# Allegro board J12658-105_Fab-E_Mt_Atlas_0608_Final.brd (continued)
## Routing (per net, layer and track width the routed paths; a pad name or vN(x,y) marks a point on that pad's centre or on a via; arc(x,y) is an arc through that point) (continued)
MUX_CTRL_3: length 30.1
  TOP w0.127: v1(28.19,27.3) 28.06,27.44 U28.1
  L3_SIG w0.127: SW4.3 16.64,14.22 16.64,16.13 17.16,16.65 17.89,16.65 17.91,16.64 18.35,16.64 18.81,17.09 18.81,19.42 v1(18.54,19.69) ; v1(28.19,27.3) 28.19,26.78 27.62,26.2 27.62,21.39 27.37,21.14 v1(26.49,21.14)
  L4_SIG w0.127: v1(26.49,21.14) 25.04,19.69 23.93,19.69 23.91,19.67 23.59,19.67 23.57,19.69 v1(18.54,19.69)
  BOTTOM w0.127: R246.2 20.32,12.19 20,11.87 18.99,11.87 SW4.3
MUX_CTRL_4: length 45.9
  TOP w0.127: U19.1 v1(15.62,41.77)
  L3_SIG w0.127: v1(11.18,42.13) 11.44,41.87 11.44,38.74 11.13,38.43 11.13,38.23 11.1,38.2 11.1,37.87 11.13,37.85 11.13,36.81 11.46,36.48 11.46,36.44 11.62,36.28 11.62,14.94 13.85,12.71 13.85,11.61 14.15,11.32 14.78,11.32 15.18,10.92 17.4,10.92 SW4.4
  L4_SIG w0.127: v1(11.18,42.13) 11.54,41.77 v1(15.62,41.77)
  BOTTOM w0.127: SW4.4 18.67,11.18 R249.2
PB0_BTN: length 2.9
  TOP w0.127: SW1.2 38.99,67.46 v1(40.17,67.46)
  BOTTOM w0.127: v1(40.17,67.46) 40.17,68.09 R136.1 R137.2
PB1_BTN: length 2.8
  TOP w0.127: v1(42.35,67.44) 42.38,67.46 43.43,67.46 SW2.2
  BOTTOM w0.127: R135.1 R134.2 42.48,67.56 v1(42.35,67.44)
PLT_REG_EN: length 2.9
  TOP w0.127: U22.K3 v1(36.58,37.17)
  BOTTOM w0.127: v1(36.58,37.17) 36.99,37.57 37.57,37.57 38.16,38.16 R262.2
RESET_BTN: length 4.2
  TOP w0.127: S1.2 65.75,74.1 v1(64.85,74.1)
  BOTTOM w0.127: U31.2 64.92,72.27 64.77,72.42 64.77,72.96 64.29,73.44 Q1.3 64.29,73.76 64.64,74.1 v1(64.85,74.1)
RF_1: length 1.9
  TOP w0.229: U29.17 43.82,14.55 43.42,14.15 43.42,13.67 RF1.4
RF_2: length 1.9
  TOP w0.229: RF1.3 45.22,13.67 45.22,14.15 44.82,14.55 U29.19
RF_3: length 1.5
  TOP w0.229: L7.1 46.51,12.37 RF1.1
RF_4: length 2.3
  TOP w0.229: L8.1 L7.2
RF_5: length 1.6
  TOP w0.254: FL1.1 44.7,9.2 44.72,9.22 L8.2
RF_6: length 1.3
  TOP w0.254: L9.1 45.85,8.2 FL1.4
RF_ANT: length 4.9
  TOP w0.229: L10.2 C43.1 44.89,3.15 RF2.3 RF2.1
RF_ANT_R: length 2.8
  TOP w0.229: R118.2 R120.1 C42.1 L10.1
RF_EXT_ANT: length 4
  TOP w0.229: J13.1 44.2,6.86 44.58,7.24 R120.2
RSTOUT_N: length 8.1
  TOP w0.127: v1(44.39,59.75) 44.08,59.75 43.61,59.29 U11.5 ; R8.2 v1(45.97,64.52)
  L3_SIG w0.127: v1(45.97,64.52) 45.97,63.5 44.39,61.91 v1(44.39,59.75)
TMP_I2C_ADDRESS: length 3.9
  TOP w0.127: v1(42.55,29.85) 42.55,30.35 42.81,30.62 U21.4
  BOTTOM w0.127: R204.1 43.37,29.02 v1(42.55,29.85) 42.48,29.91 R203.2
UART1_CTS_FTD: length 52.5
  TOP w0.127: U20.10 22.12,43.97 21.59,43.43 21.34,43.43 20.95,43.81 20.95,44.45 v1(21.46,44.96) ; v1(54.67,54.42) 55.56,54.42 56.19,55.05 U9.14
  L3_SIG w0.127: v1(21.59,53.9) 21.13,53.44 21.13,48.57 21.94,47.77 21.94,45.43 v1(21.46,44.96)
  L4_SIG w0.127: v1(54.67,54.42) 54.67,53.09 54.37,52.78 53.78,52.78 52.84,51.84 50.91,51.84 50.31,51.23 48.21,51.23 48.08,51.36 46.45,51.36 46.33,51.23 43.21,51.23 42.98,51.46 42.98,51.52 40.65,53.84 38.99,53.84 38.66,53.52 35.3,53.52 34.68,54.14 21.83,54.14 v1(21.59,53.9)
UART1_CTS_HDR_HDR: length 5.9
  TOP w0.203: R21.1 64.77,54.61 66.04,55.88
UART1_RTS_FTD: length 52.2
  TOP w0.127: U20.13 24.13,45.92 24.51,46.3 v1(24.51,47.88) ; v1(58.04,51.12) 58.04,51.82 56.58,53.28 55.18,53.28 54.1,54.36 54.1,55.75 54.39,56.04 U9.12
  L4_SIG w0.127: v1(58.04,51.12) 58.46,51.12 59.31,50.27 59.31,49.42 56.5,46.61 54.29,46.61 54.03,46.34 50.04,46.34 49.25,47.13 48.92,47.13 48.64,46.85 43.63,46.85 42.62,47.87 36.72,47.87 35.93,48.65 31.64,48.65 30.75,47.77 26.55,47.77 26.42,47.64 25.9,47.64 25.66,47.88 v1(24.51,47.88)
UART1_RTS_HDR_HDR: length 5.9
  TOP w0.203: 66.04,53.34 64.77,52.07 R26.1
UART1_RXD_FTD: length 65.8
  TOP w0.127: v1(18.67,44.96) 18.33,44.62 U20.6 ; v1(56.52,54.74) 56.59,54.81 U9.15
  L3_SIG w0.127: v1(55.56,60.39) 55.56,55.69 v1(56.52,54.74) ; v1(20.19,58.04) 19.94,57.78 17.21,57.78 16.84,57.42 16.84,57.02 17.14,56.72 18.59,56.72 20.27,55.04 20.27,53.54 18.62,51.89 18.62,49.27 19.15,48.73 19.15,45.44 v1(18.67,44.96)
  L4_SIG w0.127: v1(55.56,60.39) 55.56,60.5 53.95,62.12 46.62,62.12 45.72,61.21 39.88,61.21 38.61,59.94 29.46,59.94 28.99,59.47 21.63,59.47 v1(20.19,58.04)
UART1_RXD_HDR_HDR: length 5.9
  TOP w0.203: 66.04,58.42 64.77,57.15 R18.1
UART1_TXD_FTD: length 65.9
  TOP w0.127: U9.13 54.95,55.47 v1(54.86,55.56) ; v1(18.67,46.99) 18.25,46.57 U20.3
  L3_SIG w0.127: v1(18.67,46.99) 18.05,47.61 18.05,51.46 18.05,51.64 18.75,52.35 18.75,53.44 18.35,53.85 17.84,53.85 17.69,53.69 17.12,53.69 16.92,53.89 16.92,54.57 16.51,54.98 16.51,57.98 17.21,58.67 19.56,58.67 v1(19.88,58.99) ; v1(54.86,55.56) 54.36,56.07 54.36,59.82 55.44,60.9 v1(56.13,60.9)
  L4_SIG w0.127: v1(19.88,58.99) 20.59,59.7 24.74,59.7 25.36,60.32 38.16,60.32 39.37,61.53 45.71,61.53 47.82,63.64 53.39,63.64 v1(56.13,60.9)
UART1_TXD_HDR_HDR: length 5.9
  TOP w0.203: 66.04,60.96 64.77,59.69 R14.1
UART_MUX_SEL: length 4.6
  TOP w0.127: v1(18.67,48.01) 18.53,47.87 U20.1
  BOTTOM w0.127: 17.65,45.97 R188.1 v1(18.67,48.01)
UART_RX_DIR: length 2.9
  TOP w0.203: U9.5 56.99,58 57.66,58.67 v1(57.91,58.67)
  BOTTOM w0.127: R146.1 57.66,58.67 v1(57.91,58.67)
UART_TX_DIR: length 3.1
  TOP w0.127: v1(57.91,57.78) 57.37,57.24 U9.4
  BOTTOM w0.127: v1(57.91,57.78) 58.44,58.32 58.44,58.9 R145.2
UNNAMED_6_HDR2X22_I187_37: length 13
  BOTTOM w0.203: R241.2 12.17,14.48 11.41,13.72 11.41,12.64 10.52,11.75 7.49,11.75 7.24,11.49 3.87,11.49 J15.37
UNNAMED_11_RES_I77_B: length 2.4
  TOP w0.127: U21.3 43.77,32.62 43.43,32.96 v1(43.43,33.59)
  BOTTOM w0.127: R197.2 v1(43.43,33.59)
UNNAMED_12_CAP_I18_A: length 3.9
  TOP w0.127: C32.1 48.13,21.34 48.01,21.21 48.01,19.37 47.42,18.78 U29.27
UNNAMED_12_CC2520RHDT_I96_RBIAS: length 1.9
  TOP w0.127: U29.23 47.74,16.78 48.01,16.51 R110.1
UNNAMED_13_CAP_I46_A: length 4
  TOP w0.127: U30.41 v1(19.69,5.72)
  BOTTOM w0.127: v1(19.69,5.72) 19.69,6.73 20.19,7.24 C95.1
UNNAMED_14_LED_I15_C: length 1
  TOP w0.127: D2.2 R1.1
UNNAMED_15_RES_I26_B: length 1.9
  TOP w0.127: U15.7 18.92,50.48 v1(19.18,50.74)
  BOTTOM w0.127: R163.2 18.35,50.74 v1(19.18,50.74)
UNNAMED_15_RES_I27_B: length 2.8
  TOP w0.127: U15.3 14.86,49.98 v1(14.61,49.72)
  BOTTOM w0.127: R165.2 15.56,50.16 15.11,49.72 v1(14.61,49.72)
UNNAMED_17_FERRITE_I54_A: length 8
  TOP w0.508: FB3.1 14.22,68.2 12.26,70.17 12.26,72.96 J3.3
UNNAMED_18_DMN1150UFB7B_I109_3: length 0.9
  TOP w0.127: R133.2 55.82,69.02 Q2.3
UNNAMED_18_RES_I145_B: length 3.1
  TOP w0.508: R7.2 J6.1
UNNAMED_19_CAP_I58_A: length 3
  TOP w0.127: U11.6 43.11,57.15 v1(42.35,56.39)
  BOTTOM w0.127: C62.1 v1(42.35,56.39)
UNNAMED_19_CAP_I85_A: length 3
  TOP w0.508: U5.5 31.75,64.65 v1(31.81,64.58) FB5.2
  BOTTOM w0.381: v1(31.81,64.58) 31.88,64.64 C51.1
UNNAMED_19_LED_I28_C: length 1.2
  TOP w0.127: D1.2 R4.1
UNNAMED_19_RES_I88_B: length 3
  TOP w0.127: v1(29.85,67.07) 29.85,67.07 U5.3
  BOTTOM w0.127: R138.2 30.1,67.88 29.85,67.64 v1(29.85,67.07)
USB_FTD_DM: length 11.9
  TOP w0.21: v1(48.32,60.83) 48.09,61.07 48.09,61.24 48.2,61.35 L2.2 ; U11.8 42.11,59.61 v1(41.97,59.75)
  L3_SIG w0.152: v1(41.97,59.75) 41.97,58.98 42.91,58.05 44.86,58.05 45.6,58.79 47.5,58.79 48.12,59.42 48.12,60.63 v1(48.32,60.83)
USB_FTD_DP: length 11.8
  TOP w0.21: v1(42.86,59.75) 42.85,59.75 42.61,59.51 U11.7 ; L2.3 47.65,61.39 47.73,61.3 47.73,60.94 v1(47.62,60.83)
  L3_SIG w0.152: v1(42.86,59.75) 42.86,60.01 42.74,60.12 42.59,60.12 42.42,59.96 42.42,58.96 43.03,58.35 44.73,58.35 45.47,59.09 47.37,59.09 47.82,59.54 47.82,60.64 v1(47.62,60.83)
V_BATT: length 12.2
  TOP w0.508: v1(21.97,64.26) 21.21,63.5 F1.2
  BOTTOM w0.508: v1(21.97,64.26) 22.48,64.77 22.48,69.08 J4.2
V_BATT_FUSE: length 3.1
  TOP w0.254: 19.05,60.64 D8.2
  TOP w0.508: F1.1 19.56,59.69 19.05,60.2 19.05,60.64
V_BATT_FUSE_D: length 15.2
  TOP w0.254: 19.05,61.72 D8.1
  TOP w0.508: 19.05,61.72 19.05,62.74 v1(18.67,63.12) ; 16.37,67.5 15.8,66.93 FB3.2 ; 16.37,67.5 v1(17.46,67.5) ; 16.37,67.5 16.35,67.51 16.35,69.88 14.99,71.25 J5.3
  BOTTOM w0.508: v1(18.67,63.12) 18.67,64.9 18.73,64.96 18.73,66.23 v1(17.46,67.5)
V_BB_3P8: length 65.6
  TOP w0.381: R3.1 R2.1 39.5,71.5 v1(39.24,71.75) ; v1(7.76,61.77) R13.1
  L4_SIG w0.635: J3.1 6.41,74.17 5.4,73.15 5.4,59.37 v1(7.51,57.26) v1(8.33,57.26)
  BOTTOM w0.305: J3.1 9.82,72.73 16.34,72.73 18.16,74.55 26.92,74.55 28.89,72.58 28.89,70.8 29.46,70.23 36.39,70.23 36.83,69.79 38.73,69.79 39.24,70.29 v1(39.24,71.75)
  BOTTOM w0.381: v1(7.76,61.77) 7.51,61.51 v1(7.51,57.26)
V_BB_EN: length 4
  TOP w0.127: v1(13.29,61.38) 13.29,60.88 13.07,60.66 U40.6
  BOTTOM w0.254: R15.2 14.05,60.62 v1(13.29,61.38)
V_BB_FB: length 2.1
  TOP w0.305: U40.10 9.71,60.66 R144.1
  TOP w0.381: R13.2 R144.1
V_BB_L1: length 0.7
  TOP w0.254: 12.21,57.7 12.12,57.79 U40.4
V_BB_L2: length 0.7
  TOP w0.254: 11.13,57.64 11.13,58.33 U40.2
V_BB_PS: length 3.8
  TOP w0.127: v1(12.5,61.39) 12.53,61.39 12.53,61.38 12.27,61.38 12.12,61.23 U40.7
  BOTTOM w0.254: R142.1 12.14,61.03 v1(12.5,61.39) 13.1,60.79 R143.2
V_BB_VINA: length 1.2
  TOP w0.254: U40.8 11.62,61.62 C55.1
VOLT_SEL: length 84.7
  TOP w0.127: v1(52.45,69.91) 53.11,69.25 Q2.1 ; v1(47.75,30.99) 47.77,31.01 U18.2
  TOP w0.203: U24.1 43.69,29.59 v1(43.43,29.85)
  L3_SIG w0.127: v1(52.45,69.91) 52.45,69.42 51.56,68.53 51.53,68.53 50.24,67.24 50.24,63.96 50.04,63.75 49.47,63.75 49.07,63.36 49.07,58.56 47.17,56.65 47.17,43.83 48.36,42.63 48.36,31.6 v1(47.75,30.99) 47.39,30.99 46.49,31.89 45.43,31.89 43.43,29.89 v1(43.43,29.85)
  L4_SIG w0.127: v1(52.45,69.91) 52.44,69.9 51.63,69.9 50.05,68.32 26.92,68.32 v1(25.78,67.18)
  BOTTOM w0.127: J6.2 25.27,63.25 25.78,63.75 v1(25.78,67.18)
VOLT_SEL_N: length 4.5
  TOP w0.127: U24.4 44.79,28 46,28 46.52,27.48 47.28,27.48 47.77,27.97 U8.2
VSYS: length 196.6
  TOP w0.203: U8.1 47.37,28.17 47.14,27.94 v1(46.74,27.94) ; U24.5 44.54,29.49 44.64,29.59 v1(45.09,29.59) ; v1(46.74,30.99) 47.37,31.62 U18.1
  TOP w0.254: U27.1 v1(51.44,30.99)
  TOP w0.381: U1.6 60.98,74.08 v1(60.99,74.07) ; U36.5 62.73,73.97 v1(62.74,73.98) ; 60.96,71.12 60.64,70.8 U2.6 ; 60.96,71.12 61.19,70.89 U36.1 ; 60.96,71.12 v1(60.96,71.25)
  TOP w0.508: R7.1 27.24,67.63 25.56,69.31 v1(24.19,69.31) ; SW3.2 6.54,66.61 FB1.1 7.41,67.62 7.88,68.09 v1(7.88,69.59)
  L3_SIG w0.381: v1(51.44,30.99) 49.22,28.77 47.57,28.77 ; 47.57,28.77 v1(46.74,27.94) v1(45.09,29.59) ; 47.57,28.77 47.57,30.28 46.86,30.99 v1(46.74,30.99)
  L3_SIG w0.635: v1(54.23,67.31) 54.23,66.61 v1(53.98,66.36) 53.98,64.1 56.35,61.72 59.27,61.72 62.15,58.84 62.15,33.34 v1(61.4,32.59) v1(61.4,31.56)
  L4_SIG w0.508: v1(60.96,71.25) 60.01,72.2 60.01,74.07 ; 60.01,74.07 v1(60.99,74.07) 61.07,73.99 61.2,73.99 61.21,73.98 v1(62.74,73.98) 63.18,73.98 64.01,74.8 v1(64.77,74.8) ; 60.01,74.07 58.62,74.07 57.66,75.03 56.62,75.03 55.5,73.91 v1(53.21,73.91) ; v1(51.44,30.99) 50.8,31.62 50.8,32.05 50.22,32.64 46.29,32.64 46.16,32.51 v1(42.55,32.51) v1(41.72,32.51)
  L4_SIG w0.635: 53.21,73.41 52.2,73.41 51.94,73.15 28.07,73.15 24.22,69.31 v1(24.19,69.31) 18.32,69.31 14.92,72.71 7.81,72.71 6.98,71.88 6.98,70.48 v1(7.88,69.59) ; 53.21,73.41 v1(53.21,72.83) ; 53.21,73.41 v1(53.21,73.91) ; v1(61.4,32.59) v1(61.4,31.56) 60.83,31.56 59.05,33.34 57.75,33.34 55.4,30.99 v1(51.44,30.99)
  BOTTOM w0.254: R279.1 9.14,56.07 8.95,56.26 6.86,56.26 6.1,57.02 6.1,60.83 SW3.2
  BOTTOM w0.381: C103.1 v1(62.74,73.98) ; C72.1 v1(46.74,27.94) ; v1(64.77,74.8) 65.15,74.8 65.53,74.42 R125.1 ; C90.1 51.37,30.92 v1(51.44,30.99) ; R131.1 60.39,71.25 v1(60.96,71.25) 61.72,71.25 C48.1 ; C99.1 v1(46.74,30.99) ; C91.1 v1(41.72,32.51) v1(42.55,32.51) ; C100.1 44.64,29.15 v1(45.09,29.59) ; R124.1 60.49,74.07 v1(60.99,74.07) 61.43,74.07 C45.1
  BOTTOM w0.635: v1(53.21,73.91) v1(53.21,72.83) 53.21,68.33 v1(54.23,67.31) 54.04,67.12 54.04,66.42 v1(53.98,66.36)
VSYS_ADC_SENSE: length 3.2
  BOTTOM w0.127: R280.1 C97.1 R127.2 R279.2
VSYS_DISCH: length 3.3
  TOP w0.508: SW3.3 6.01,61 R17.1
VSYS_SENSE: length 13.7
  TOP w0.508: SW3.1 3.43,67.7 4.62,68.89 6.54,68.89 FB1.2 6.54,72.07 7.16,72.7 9.45,72.7 J3.2
XVREF: length 59.9
  TOP w0.127: R42.2 v1(54.61,44.2)
  L3_SIG w0.127: v1(54.86,49.15) 54.34,48.63 54.34,47.23 54.24,47.13 54.24,44.56 v1(54.61,44.2) 55.09,44.2 55.8,43.49 55.8,11.35 54.99,10.54 v1(53.91,10.54)
  L4_SIG w0.127: v1(54.86,49.15) 54.17,49.15 53.94,48.92 53.14,48.92 52.92,48.71 47.82,48.71 47.11,47.99 44.14,47.99 43.31,48.82 40.06,48.82 v1(39.5,48.26)
  BOTTOM w0.127: R252.2 v1(53.91,10.54) ; R169.1 v1(39.5,48.26)
XVREF_HDR: length 11.8
  BOTTOM w0.203: R252.1 56.52,10.54 57.9,9.16 60.87,9.16 61.21,8.83 64.83,8.83 J14.46

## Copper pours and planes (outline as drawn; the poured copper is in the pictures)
AVDD_B_RADIO on TOP: 40.39,14.48 40.39,13.91 40.89,13.91 40.89,14.41 41.4,14.41 41.4,13.91 41.91,13.91 41.91,14.41 42.23,14.41 42.23,16.38 41.47,16.38 41.47,15.56
GND on TOP (solid shape): 10.22,60.12 11.02,60.12 11.02,60.13 11.22,60.13 11.22,60.12 13.03,60.12 13.03,60.13 14.48,60.13 14.61,60.01 14.61,59.18 13.84,59.18 13.84,59.1 13.35,59.1 13.16,58.91 10.62,58.91 10.49,59.04 8.66,59.04 8.66,60.06 8.74,60.13 10.22,60.13
GND on BOTTOM (solid shape): 12.59,59.67 12.59,59.31 12.46,59.18 8.38,59.18 8.38,59.94 12.32,59.94
GND on TOP: 48.13,4.55 48.13,8.64 47.88,8.89 47.88,11.94 47.5,12.32 44.32,12.32 44.32,11.68 44.07,11.68 44.07,9.78 43.05,9.78 42.67,9.4 42.67,8.89 39.05,8.89 39.05,4.55
GND on TOP: 68.01,1.21 67.44,0.64 53.34,0.64 53.34,4.55 15.24,4.55 15.24,0.64 1.08,0.64 0.57,1.14 0.57,74.99 1.21,75.63 67.37,75.63 68.01,74.99 ; 25 cut-outs
GND on BOTTOM: 68.01,1.21 67.44,0.64 53.34,0.64 53.34,4.7 15.24,4.7 15.24,0.64 1.08,0.64 0.57,1.14 0.57,74.99 1.21,75.63 67.37,75.63 68.01,74.99 ; 17 cut-outs
GND on LAYER2_GND: 1.03,0.64 0.64,1.03 0.64,75.17 1.03,75.56 67.55,75.56 67.94,75.17 67.94,1.03 67.55,0.64 53.34,0.64 53.34,4.64 24.51,4.64 24.51,0.64
VBAT_SOC on TOP: 39.37,33.4 39.05,33.72 38.35,33.72 38.21,33.57 38.21,31.54 37.98,31.3 37.97,30.1 38.42,29.65 39.12,29.65 39.37,29.91
VBAT_SOC on L3_SIG: 36.45,36.96 38.3,36.96 39.27,35.99 39.27,31.46 38.86,31.05 37.78,31.05 37.3,31.54 37.3,33.81 36.2,34.91 36.2,36.7
VCC_AON_1P8 on LAYER5_PWR: 36.76,30.35 35.56,31.55 35.56,33.45 33.59,35.42 33.59,39.43 36.07,39.43 36.07,37.6 36.65,37.02 37.35,37.02 39.88,34.49 39.88,31.68 38.56,30.35
VCC_HOST_1P8 on TOP: 41.97,40.83 41.53,41.27 41.53,42.65 45.11,42.65 45.34,42.42 45.34,41.08 45.09,40.83
VCC_HOST_1P8 on LAYER5_PWR: 36.32,39.31 36.32,39.69 33.59,39.69 33.59,41.85 40.12,41.85 41.84,43.56 45.41,43.56 45.59,43.38 45.59,40.51 42.56,40.51 41.73,39.69 38.05,39.69 37.67,39.31
VCC_IO on LAYER5_PWR: 6.73,0.64 6.73,64.46 10.85,68.58 35.99,68.58 37.77,70.36 52.63,70.36 53.77,71.5 56.64,71.5 57.59,72.45 58.48,72.45 58.61,72.33 58.61,71.64 61.72,68.53 61.72,65.15 41.86,65.15 36.27,59.56 30.68,59.56 29.84,58.73 29.84,56.45 30.92,55.37 31.69,55.37 32.32,56.01 32.83,56.01 33.4,55.44 33.4,54.48 35.18,52.7 38.05,52.7 41.86,48.89 47.05,48.89 47.75,48.2 47.75,46.8 48.58,45.97 55.56,45.97 57.4,47.82 57.4,56.01 61.72,56.01 61.72,0.64 53.34,0.64 53.34,4.7 15.24,4.7 15.24,0.64 ; 2 cut-outs
VCC_IO_AON on BOTTOM: 35.12,41.78 35.12,43.81 34.73,44.2 33.78,44.2 33.46,43.88 33.46,41.59 32.43,40.56 32.43,40.04 32.26,39.87 32.26,39.5 32.32,39.43 32.77,39.43 32.78,39.45 33.36,39.45 33.78,39.88 33.78,40.45
VCC_PLT_1P8 on TOP: 44.7,34.73 41.85,34.73 41.47,35.12 41.47,36.77 41.78,37.08 43.56,37.08 43.75,36.89 43.75,36.32 43.94,36.13 44.64,36.13 44.83,35.94 44.83,34.86
VCC_PLT_1P8 on LAYER5_PWR: 40.06,34.67 37.45,37.27 36.76,37.27 36.32,37.71 36.32,38.29 38.24,38.29 38.62,37.91 39.32,37.91 40.02,37.21 45.59,37.21 45.59,34.67
VCC_PLT_3P3 on TOP: 41.85,37.66 43.94,37.66 43.94,39.56 44.01,39.62 44.01,40.32 43.81,40.51 42.04,40.51 41.47,39.94 41.47,38.04
VCC_PLT_3P3 on LAYER5_PWR: 40.12,37.46 39.42,38.16 38.72,38.16 38.34,38.54 36.32,38.54 36.32,39.05 37.77,39.05 38.15,39.43 41.84,39.43 42.66,40.26 45.59,40.26 45.59,37.46
VCC_RADIO on LAYER5_PWR: 36.45,11.3 36.45,26.29 51.75,26.29 51.75,11.42 51.64,11.3
VDD_HDR on L3_SIG: 59.18,68.83 10.67,68.83 6.48,64.64 6.48,0.64 1.08,0.64 0.63,1.08 0.63,75.12 1.08,75.56 67.44,75.56 68.07,74.93 68.07,1.21 67.5,0.64 61.98,0.64 61.98,66.04
VDD_HDR on LAYER5_PWR: 1.03,0.64 0.26,1.41 0.26,74.79 1.15,75.69 67.43,75.69 68.32,74.79 68.32,1.41 67.55,0.64 61.98,0.64 61.98,68.63 58.86,71.75 58.86,72.46 58.61,72.71 57.47,72.71 56.52,71.75 53.67,71.75 52.53,70.61 37.67,70.61 35.89,68.83 10.74,68.83 6.48,64.57 6.48,0.64
(no net) on TOP: 13.16,58.91 13.35,59.1 14.61,59.1 14.61,60.01 14.48,60.13 8.74,60.13 8.66,60.06 8.66,59.04 10.49,59.04 10.62,58.91
(no net) on TOP: 12.02,58.59 12.02,57 12.34,56.69 12.34,54.08 13.16,54.08 13.16,57 12.27,57.89 12.27,58.59
(no net) on TOP: 10.75,58.53 7.11,58.53 7.11,57.21 7.32,57 9.67,57 10.75,58.08
(no net) on TOP: 11.26,58.59 11,58.59 11,57.83 10.18,57 10.18,54.08 10.94,54.08 10.94,56.75 11.26,57.07
(no net) on TOP: 12.46,58.65 14.54,58.65 14.54,57.78 12.83,57.78 12.79,57.75 12.46,58.08
(no net) on BOTTOM: 12.32,59.94 8.38,59.94 8.38,59.18 12.46,59.18 12.59,59.31 12.59,59.67
(no net) on BOTTOM: 8.38,58.55 8.25,58.42 8.25,58.04 7.75,57.53 7.38,57.53 7.26,57.4 7.26,57.19 7.43,57.02 9.4,57.02 10.29,57.91 10.29,58.8 9.65,58.8 9.4,58.55
AP_USB_5V on TOP: 36.89,67.31 35.56,67.31 35.56,65.66 35.75,65.47 36.89,65.47 37.02,65.6 37.02,67.18
AP_VBUS on TOP: 35.41,70.94 35.41,69.67 35.56,69.52 35.56,68.26 36.77,68.26 36.77,69.41 36.32,69.85 36.32,70.93 36.13,71.12 35.81,71.12 35.46,71.48 35.46,72.59 35.33,72.72 35,72.72 35,71.35
BEST_OF_SUPPLY on TOP (solid shape): 14.54,57.78 12.83,57.78 12.79,57.75 12.52,58.02 12.52,58.65 12.87,58.65 12.87,58.65 14.54,58.65
FTD_3P3 on LAYER5_PWR: 41.97,49.14 40.82,50.29 38.15,52.96 35.24,52.96 33.66,54.55 33.66,55.56 32.96,56.26 32.19,56.26 31.56,55.63 31.05,55.63 30.1,56.58 30.1,58.62 30.53,59.05 36.12,59.05 41.96,64.9 61.72,64.9 61.72,56.26 57.15,56.26 57.15,47.94 55.44,46.23 48.7,46.23 48.01,46.93 48.01,48.32 47.18,49.15 47.17,49.14
FTD_VBUS on TOP: 49.23,70.69 49.23,69.22 49.37,69.07 49.37,68.07 49.88,67.56 50.45,67.56 50.45,70.52 50.01,70.96 50.01,70.93 49.82,71.12 49.48,71.12 49.15,71.45 49.15,72.64 49.07,72.72 48.72,72.72 48.72,71.2
V_BB_3P8 on TOP (solid shape): 10.72,58.05 9.67,57 7.32,57 7.11,57.21 7.11,58.53 10.72,58.53
V_BB_3P8 on BOTTOM (solid shape): 10.29,57.91 9.4,57.02 7.43,57.02 7.26,57.19 7.26,57.4 7.38,57.53 7.75,57.53 8.25,58.04 8.25,58.42 8.38,58.55 9.4,58.55 9.65,58.8 10.29,58.8
V_BB_L1 on TOP (solid shape): 12.21,57.98 12.22,57.97 12.22,57.8 12.37,57.8 13.16,57 13.16,54.08 12.34,54.08 12.34,56.69 12.02,57 12.02,57.8 12.02,57.8 12.02,58.59 12.21,58.59
V_BB_L2 on TOP (solid shape): 11.22,57.8 11.26,57.8 11.26,57.07 10.94,56.75 10.94,54.08 10.18,54.08 10.18,57 10.97,57.8 11.02,57.8 11.02,58.59 11.22,58.59
VSYS on TOP: 40.36,33.53 40.36,32.26 42.55,32.26 42.8,32.51 42.55,32.77 42.16,32.77 41.4,33.53

Small or netless copper shapes (teardrops, artwork), in the pictures only: 2 on TOP

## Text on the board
BOTTOM: J12658-105
User.Comments: CR_X1_1 | CR_S1_1 | JUN 08 | FAB B RELEASE | FAB C RELEASE | FAB D RELEASE | FAB E RELEASE
Ref Des/Assembly Top: 1 | 2 | 44 | 49
Ref Des/Silkscreen Top: GND | 3.3V | A3 | VIN | A0 | A4 | A1 | A2 | A5 | 5V | USB | CTRL2 | CTRL3 | CTRL1 | CTRL4 | BATT | 1.8V | VCC_IO_AON | D8 | D9 | D13 | D7 | AREF | D12 | D11 | D10 | D6 | TX 1 | D5 | D4 | RX 0 | D3 | D2 | IOREF | RESET | LED0 | LED1 | ON | OFF | 1 | ATP_USB | PB0 | PB1 | FTD_USB | MAX5V
DISPLAY_TOP: R39 | C41 | C39 | C38 | C37 | C33 | C34 | C35 | C36 | C31 | C32 | FB4 | C29 | CR1 | L2 | C24 | C25 | C22 | C23 | C21 | C20 | C15 | C14 | C4 | C7 | C5 | C6 | C8 | C3 | C1 | C43 | R31 | R34 | R29 | R30 | R32 | R33 | R28 | R27 | R21 | R22 | R23 | R24 | R19 | R18 | R25 | R26 | R17 | R12 | R13 | R11 | R9 | R7 | R3 | Q1 | 6 | R43 | DS1 | J25 | J23 | J22 | D2 | MH* | J24 | J21 | J20 | J19 | Q4 | C42 | C40 | U5 | J18 | J17 | U4 | L3 | J16 | D1 | J15 | J14 | J13 | BT2 | C30 | U3 | C28 | C27 | J12 | C26 | Q3 | C19 | FB3 | C18 | J11 | C17 | Q2 | C16 | Y2 | L1 | J10 | C13 | C12 | C11 | FB2 | J7 | J9 | J8 | C9 | C10 | FB1 | C2 | Y1 | U1 | TP1 | TP2 | TP3 | J5 | J6 | SW1 | J4 | J2 | J3 | J1 | DS2 | R42 | R41 | R40 | R38 | R37 | F1 | R36 | R35 | R20 | R16 | R15 | R14 | Y3 | R10 | U2 | R8 | R6 | R5 | R4 | R2 | R1 | 8 | 1 | 10 | 5 | 2
User.6: 2 | LAYER(S) | 1 | TRACE | WIDTH | (MILS) | 9.000 | SPACING | (GAP) | 6 | GAP | TO | GND | REFERENCE | LATER | REQUIRED | EMPEDANCE | 50 OHMS | +/- 10% | TOLERANCE | 9 | FEB 12 | APR 11 | MAY 13 | JUN 08 | 2016 | 24. | 25. | TRIM PAD BACK OFF THE BOARD EDGE 25 MILS, 2 PLACES, ON THE SOUTH OF BOARD, TOP AND BOTTOM. | PLEASE ROUTE ALONG THESE EDGES. | 8 | 05 | 04 | 02 | 03 | IMPEDANCE CHART | JRC
User.17: 3 | 4
User.18: FEB 12 | APR 11 | MAY 13 | JUN 08 | 2016 | 02 | 03 | 04 | 05 | JRC | PRIMARY SIDE | SECONDARY SIDE
User.31: (REF) | 45 X0.030 | 4 PLACES
User.32: SECONDARY VIEW
User.45: FIGURE | SIZE | 8.0 | 31.0 | 32.0 | 40.0 | 43.31 | 55.12 | 118.0 | 63.0 | 33.0x26.0 | 60.0x32.0 | DRILL CHART: TOP to BOTTOM | ALL UNITS ARE IN MILS | TOLERANCE | +0.0/-8.0 | +3.0/-3.0 | +4.0/-4.0 | PLATED | NON-PLATED | QTY | 1115 | 32 | 5 | 9 | 96 | 3 | 2 | 4
